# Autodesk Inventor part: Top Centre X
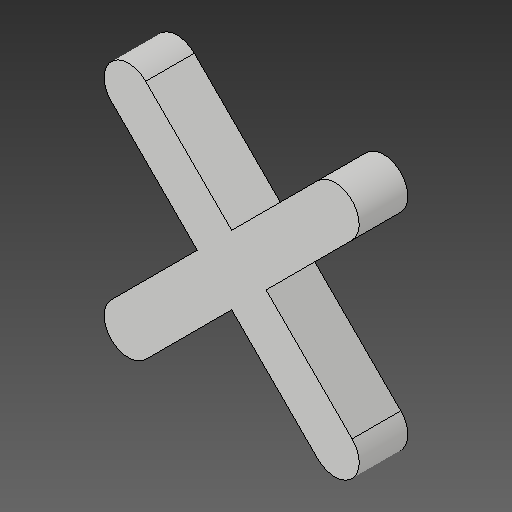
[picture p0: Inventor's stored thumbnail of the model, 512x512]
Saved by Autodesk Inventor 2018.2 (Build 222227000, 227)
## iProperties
Created: 2018-03
Part Number: Top Centre X
Material: Generic
Document SubType Name: Modeling
Designer: PeterMaxwell-Stewart
Mass: 1.57135 g
Surface Area: 12.8562 cm^2
Volume: 1.57135 cm^3
Density: 1 g/cm^3
Appearance: Default
Author: PeterMaxwell-Stewart
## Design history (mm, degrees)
derived "O's and X's.ipt"
feature "Top Centre X::O's and X's.ipt" dims "d0" = 10
tag "TaggingFeature1"
body "Solid1"
